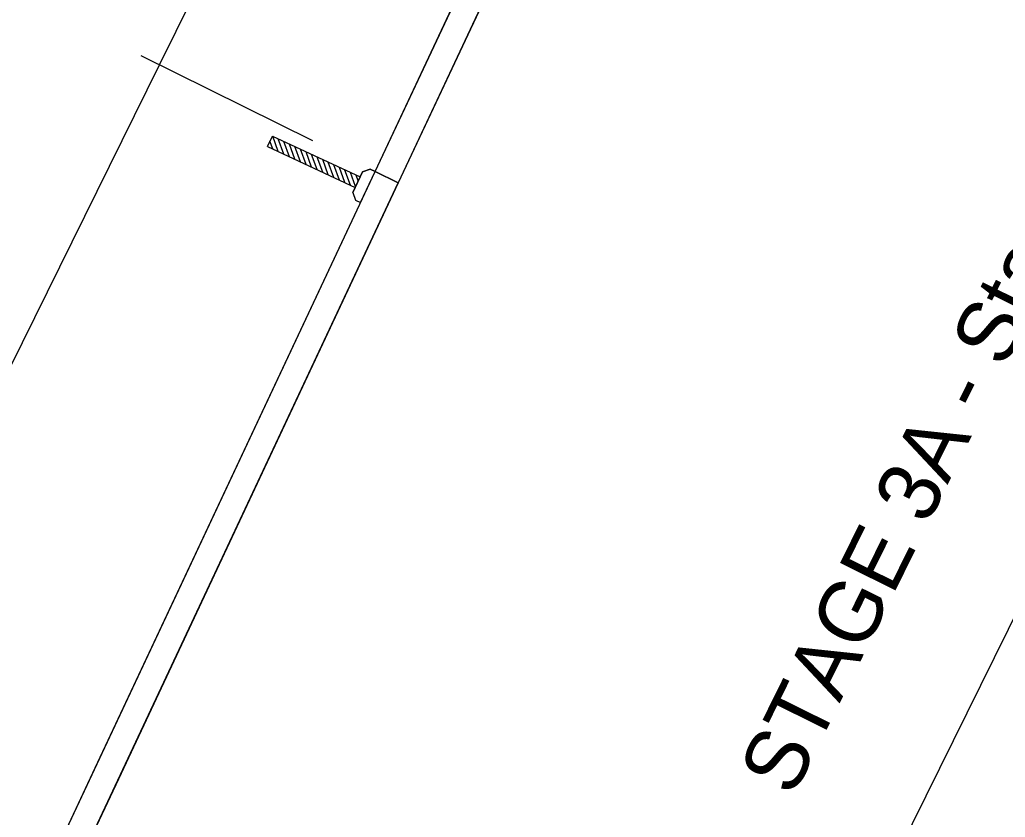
# Model space of a CAD drawing. Extents: x 14104283 to 14128447, y 8633203 to 8671666.
# Drawn here: x 14117742.5 to 14117870, y 8668618.6 to 8668721.7 of the extents above; entities that cross this region are included whole.
import ezdxf

# ---------------------------------------------------------------- set-up
doc = ezdxf.new("R2010")
doc.units = 0
for name, color, linetype in [('Cell', 7, 'Continuous'), ('dsnStgShadingPrevPav', 7, 'Continuous'), ('dsnTextFinalPlan', 7, 'Continuous'), ('TC_SubstrataExistingPavement', 7, 'Continuous'), ('Terrain', 7, 'Continuous')]:
    doc.layers.add(name, color=color, linetype=linetype)

msp = doc.modelspace()

# ---------------------------------------------------------------- linework, layer by layer
at = {"layer": 'Cell'}
for p, q in [((14117774.55, 8668705.34), (14117775.18, 8668706.68)), ((14117775.18, 8668706.68), (14117786.52, 8668701.39)), ((14117775.94, 8668704.69), (14117775.23, 8668706.66)), ((14117774.55, 8668705.34), (14117785.89, 8668700.04)), ((14117775.22, 8668705.02), (14117774.86, 8668706.01)), ((14117776.66, 8668704.35), (14117775.94, 8668706.32)), ((14117777.38, 8668704.01), (14117776.66, 8668705.99)), ((14117778.1, 8668703.68), (14117777.38, 8668705.65)), ((14117778.82, 8668703.34), (14117778.1, 8668705.32)), ((14117779.54, 8668703.01), (14117778.82, 8668704.98)), ((14117780.26, 8668702.67), (14117779.54, 8668704.64)), ((14117780.97, 8668702.34), (14117780.26, 8668704.31)), ((14117781.69, 8668702), (14117780.98, 8668703.97)), ((14117782.41, 8668701.67), (14117781.7, 8668703.64)), ((14117783.13, 8668701.33), (14117782.41, 8668703.3)), ((14117783.85, 8668700.99), (14117783.13, 8668702.97)), ((14117784.57, 8668700.66), (14117783.85, 8668702.63)), ((14117785.29, 8668700.32), (14117784.57, 8668702.29)), ((14117785.94, 8668700.16), (14117785.29, 8668701.96)), ((14117785.57, 8668699.37), (14117786.83, 8668702.06)), ((14117786.52, 8668701.39), (14117785.89, 8668700.04)), ((14117786.28, 8668700.88), (14117786.01, 8668701.62)), ((14117786.83, 8668702.06), (14117786.52, 8668701.39)), ((14117786.59, 8668698.08), (14117788.48, 8668702.11)), ((14117786.59, 8668698.08), (14117788.48, 8668702.11)), ((14117787.81, 8668702.42), (14117786.83, 8668702.06)), ((14117786.83, 8668702.06), (14117787.81, 8668702.42)), ((14117788.48, 8668702.11), (14117787.81, 8668702.42)), ((14117787.81, 8668702.42), (14117788.48, 8668702.11)), ((14117785.89, 8668700.04), (14117785.57, 8668699.37)), ((14117785.57, 8668699.37), (14117785.93, 8668698.39)), ((14117785.57, 8668699.37), (14117785.93, 8668698.39)), ((14117785.93, 8668698.39), (14117786.59, 8668698.08)), ((14117785.93, 8668698.39), (14117786.59, 8668698.08))]:
    msp.add_line(p, q, dxfattribs=at)
at = {"layer": 'dsnStgShadingPrevPav'}
for points in [[(14117788.48, 8668702.11), (14117801.31, 8668729.42), (14117804.29, 8668727.94), (14117791.47, 8668700.63)], [(14117747.28, 8668614.41), (14117752.26, 8668625.02), (14117788.48, 8668702.11), (14117791.47, 8668700.63), (14117755.25, 8668623.54), (14117750.26, 8668612.93)]]:
    msp.add_lwpolyline(points, close=True, dxfattribs=at)
at = {"layer": 'dsnTextFinalPlan'}
for p, q in [((14117760.59, 8668715.9), (14117773.96, 8668742.94)), ((14117758.14, 8668717.11), (14117780.37, 8668706.12)), ((14117717.65, 8668629.05), (14117760.59, 8668715.9))]:
    msp.add_line(p, q, dxfattribs=at)
msp.add_lwpolyline([(14117425.32, 8668197.46), (14117939.89, 8669238.2), (14118120.52, 8669148.89), (14117605.96, 8668108.15)], close=True, dxfattribs=at)
at = {"layer": 'TC_SubstrataExistingPavement'}
msp.add_line((14117719.03, 8668546.44), (14117791.47, 8668700.63), dxfattribs=at)
msp.add_lwpolyline([(14117844.93, 8668822.28), (14117847.92, 8668820.81), (14117791.47, 8668700.63), (14117788.48, 8668702.11)], dxfattribs=at)
at = {"layer": 'Terrain'}
for p, q in [((14117788.48, 8668702.11), (14117844.93, 8668822.28)), ((14117716.04, 8668547.92), (14117788.48, 8668702.11))]:
    msp.add_line(p, q, dxfattribs=at)

# ---------------------------------------------------------------- texts
at = {"layer": 'dsnTextFinalPlan'}
msp.add_text('STAGE 3A - Sta. 599+00', height=8, rotation=63.6911, dxfattribs=at).set_placement((14117842.5, 8668621.05))

doc.saveas('drawing.dxf')
